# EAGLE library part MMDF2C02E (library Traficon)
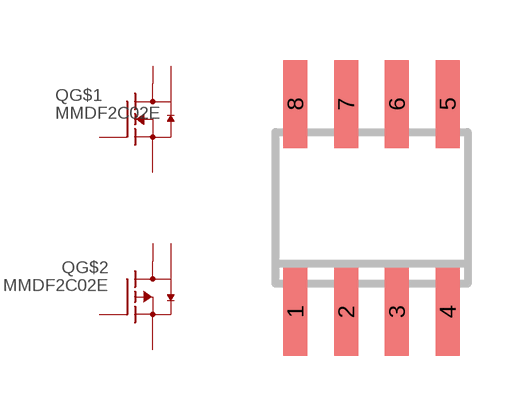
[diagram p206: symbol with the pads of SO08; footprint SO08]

Designator prefix Q; gates G$1=N-MOSFET2 G$2=P-MOSFET2

## MMDF2C02E  [SO08]
1  G$1:S  pas
2  G$1:G  pas
3  G$2:S  pas
4  G$2:G  pas
5  G$2:D  pas
6  G$2:D  pas
7  G$1:D  pas
8  G$1:D1  pas

## Footprint SO08 (pad centres in mm)
Small Outline Package
smd 0.6 x 2.2: 1 -1.905,-2.6; 2 -0.635,-2.6; 3 0.635,-2.6; 4 1.905,-2.6; 5 1.905,2.6; 6 0.635,2.6; 7 -0.635,2.6; 8 -1.905,2.6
